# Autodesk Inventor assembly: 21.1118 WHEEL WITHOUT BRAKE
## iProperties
Created: 2007-03
Part Number: 21.1118 WHEEL WITHOUT BRAKE
Document SubType Name: Assembly
Designer: Andy Moles
Author: Andy Moles
